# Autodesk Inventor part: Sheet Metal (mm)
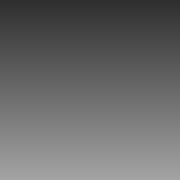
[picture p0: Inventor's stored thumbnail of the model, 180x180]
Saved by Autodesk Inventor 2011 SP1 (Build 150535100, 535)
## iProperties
Shininess: 64.0
Length Units: 11269
Angle Units: 11279
Time Units: 11290
Mass Units: 11283
Length Display Precision: 3
Angle Display Precision: 2
Compacted: True
Part Number: Sheet Metal (mm)
Document SubType Name: Sheet Metal
Created: 2002-07
Material: Default
Density: 1 g/cm^3
Sheet Metal Rule: Default_mm
Density: 0.0
Volumn: 0.0
Area: 0.0
PropertySet Name: Model Information
Control State: 0
Master: False
Checked Out: False
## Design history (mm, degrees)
other parameters: "Thickness" = 0.5, "BendRadius" = 0.5 (= Thickness), "BendReliefWidth" = 0.5 (= Thickness), "BendReliefDepth" = 0.25 (= 0.5 x Thickness), "CornerReliefSize" = 2 (= 4 x Thickness), "SeamGap" = 0.01, "MinimumRemnant" = 1 (= 2 x Thickness), "TransitionRadius" = 0.5 (= BendRadius), "JacobiRadiusSize" = 0.5 (= BendRadius), "GapSize" = 0.5 (= Thickness)
